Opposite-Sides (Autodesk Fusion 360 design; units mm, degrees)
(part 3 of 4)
sketch "Rail seat underside (1)" plane through (11.9, 0, 0) normal (1, 0, 0) x axis (0, 0, -1)
  line L1 (-50.9, 96) -> (-50.9, 75)
  line L2 (-55, 96) -> (-50.9, 96)
  line L3 (-55, 75) -> (-55, 96)
  line L4 (-50.9, 75) -> (-55, 75)
extrude "Extrude7" cut sketch "Rail seat underside (1)" along normal blind 12.2
work_plane "WorkPlane8" AlongDistance 54.9 ExtraOffset 0
sketch "M5 rail bore (1)" plane through (0, 0, 54.9) normal (0, 0, 1) x axis (1, 0, 0)
  circle C1 centre (18, 85) radius 2.7
extrude "Extrude8" cut sketch "M5 rail bore (1)" along normal blind 9.2
work_plane "WorkPlane9" AlongDistance 54.9 ExtraOffset 0
sketch "Rail bore print-up roof (1)" plane through (0, 0, 54.9) normal (0, 0, 1) x axis (1, 0, 0)
  line L1 (19.9092, 86.9092) -> (19.9092, 83.0908)
  line L2 (21.8184, 85) -> (19.9092, 86.9092)
  line L3 (19.9092, 83.0908) -> (21.8184, 85)
extrude "Extrude9" cut sketch "Rail bore print-up roof (1)" along normal blind 9.2
work_plane "WorkPlane1" AlongDistance 50 ExtraOffset 0
sketch "Top rail M5x14 (1, 1)" plane through (0, 0, 50) normal (0, 0, 1) x axis (1, 0, 0)
  circle C1 centre (18, 85) radius 2.5
extrude "Extrude1" new body sketch "Top rail M5x14 (1, 1)" along normal blind 14 bodies "HARDWARE Top rail M5x14 (1, 1)"
work_plane "WorkPlane2" AlongDistance 64 ExtraOffset 0
sketch "Button head" plane through (0, 0, 64) normal (0, 0, 1) x axis (1, 0, 0)
  circle C1 centre (18, 85) radius 4.25
extrude "Extrude2" add sketch "Button head" along normal blind 5
work_plane "WorkPlane10" AlongDistance 11.9 ExtraOffset 0
sketch "Main bearing seat" plane through (11.9, 0, 0) normal (1, 0, 0) x axis (0, 0, -1)
  circle C1 centre (-30, 0) radius 10.15
extrude "Extrude10" cut sketch "Main bearing seat" along normal blind 12.2
work_plane "WorkPlane11" AlongDistance 11.9 ExtraOffset 0
sketch "Brace mounting clearance" plane through (11.9, 0, 0) normal (1, 0, 0) x axis (0, 0, -1)
  circle C1 centre (-35, -60) radius 1.7
work_plane "WorkPlane12" AlongDistance 11.9 ExtraOffset 0
sketch "Brace mounting clearance (1)" plane through (11.9, 0, 0) normal (1, 0, 0) x axis (0, 0, -1)
  circle C1 centre (-45, -60) radius 1.7
work_plane "WorkPlane13" AlongDistance 11.9 ExtraOffset 0
sketch "Brace mounting clearance (2)" plane through (11.9, 0, 0) normal (1, 0, 0) x axis (0, 0, -1)
  circle C1 centre (-35, 60) radius 1.7
work_plane "WorkPlane14" AlongDistance 11.9 ExtraOffset 0
sketch "Brace mounting clearance (3)" plane through (11.9, 0, 0) normal (1, 0, 0) x axis (0, 0, -1)
  circle C1 centre (-45, 60) radius 1.7
work_plane "WorkPlane15" AlongDistance 11.9 ExtraOffset 0
sketch "Local measured pot and wire opening" plane through (11.9, 0, 0) normal (1, 0, 0) x axis (0, 0, -1)
  line L1 (5.5307, 7.9631) -> (6, 8)
  line L2 (5.0729, 7.8532) -> (5.5307, 7.9631)
  line L3 (4.638, 7.673) -> (5.0729, 7.8532)
  line L4 (4.2366, 7.4271) -> (4.638, 7.673)
  line L5 (3.8787, 7.1213) -> (4.2366, 7.4271)
  line L6 (3.5729, 6.7634) -> (3.8787, 7.1213)
  line L7 (3.327, 6.362) -> (3.5729, 6.7634)
  line L8 (3.1468, 5.9271) -> (3.327, 6.362)
  line L9 (3.0369, 5.4693) -> (3.1468, 5.9271)
  line L10 (3, 5) -> (3.0369, 5.4693)
  line L11 (3, -5) -> (3, 5)
  line L12 (3.0369, -5.4693) -> (3, -5)
  line L13 (3.1468, -5.9271) -> (3.0369, -5.4693)
  line L14 (3.327, -6.362) -> (3.1468, -5.9271)
  line L15 (3.5729, -6.7634) -> (3.327, -6.362)
  line L16 (3.8787, -7.1213) -> (3.5729, -6.7634)
  line L17 (4.2366, -7.4271) -> (3.8787, -7.1213)
  line L18 (4.638, -7.673) -> (4.2366, -7.4271)
  line L19 (5.0729, -7.8532) -> (4.638, -7.673)
  line L20 (5.5307, -7.9631) -> (5.0729, -7.8532)
  line L21 (6, -8) -> (5.5307, -7.9631)
  line L22 (24, -8) -> (6, -8)
  line L23 (24.4693, -7.9631) -> (24, -8)
  line L24 (24.9271, -7.8532) -> (24.4693, -7.9631)
  line L25 (25.362, -7.673) -> (24.9271, -7.8532)
  line L26 (25.7634, -7.4271) -> (25.362, -7.673)
  line L27 (26.1213, -7.1213) -> (25.7634, -7.4271)
  line L28 (26.4271, -6.7634) -> (26.1213, -7.1213)
  line L29 (26.673, -6.362) -> (26.4271, -6.7634)
  line L30 (26.8532, -5.9271) -> (26.673, -6.362)
  line L31 (26.9631, -5.4693) -> (26.8532, -5.9271)
  line L32 (27, -5) -> (26.9631, -5.4693)
  line L33 (27, 5) -> (27, -5)
  line L34 (26.9631, 5.4693) -> (27, 5)
  line L35 (26.8532, 5.9271) -> (26.9631, 5.4693)
  line L36 (26.673, 6.362) -> (26.8532, 5.9271)
  line L37 (26.4271, 6.7634) -> (26.673, 6.362)
  line L38 (26.1213, 7.1213) -> (26.4271, 6.7634)
  line L39 (25.7634, 7.4271) -> (26.1213, 7.1213)
  line L40 (25.362, 7.673) -> (25.7634, 7.4271)
  line L41 (24.9271, 7.8532) -> (25.362, 7.673)
  line L42 (24.4693, 7.9631) -> (24.9271, 7.8532)
  line L43 (24, 8) -> (24.4693, 7.9631)
  line L44 (6, 8) -> (24, 8)
extrude "Extrude15" cut sketch "Local measured pot and wire opening" along normal blind 10.3
work_plane "WorkPlane16" AlongDistance 22 ExtraOffset 0
sketch "Pot panel rebate" plane through (22, 0, 0) normal (1, 0, 0) x axis (0, 0, -1)
  line L1 (2.5307, 23.9631) -> (3, 24)
  line L2 (2.0729, 23.8532) -> (2.5307, 23.9631)
  line L3 (1.638, 23.673) -> (2.0729, 23.8532)
  line L4 (1.2366, 23.4271) -> (1.638, 23.673)
  line L5 (0.8787, 23.1213) -> (1.2366, 23.4271)
  line L6 (0.5729, 22.7634) -> (0.8787, 23.1213)
  line L7 (0.327, 22.362) -> (0.5729, 22.7634)
  line L8 (0.1468, 21.9271) -> (0.327, 22.362)
  line L9 (0.0369, 21.4693) -> (0.1468, 21.9271)
  line L10 (0, 21) -> (0.0369, 21.4693)
  line L11 (0, -21) -> (0, 21)
  line L12 (0.0369, -21.4693) -> (0, -21)
  line L13 (0.1468, -21.9271) -> (0.0369, -21.4693)
  line L14 (0.327, -22.362) -> (0.1468, -21.9271)
  line L15 (0.5729, -22.7634) -> (0.327, -22.362)
  line L16 (0.8787, -23.1213) -> (0.5729, -22.7634)
  line L17 (1.2366, -23.4271) -> (0.8787, -23.1213)
  line L18 (1.638, -23.673) -> (1.2366, -23.4271)
  line L19 (2.0729, -23.8532) -> (1.638, -23.673)
  line L20 (2.5307, -23.9631) -> (2.0729, -23.8532)
  line L21 (3, -24) -> (2.5307, -23.9631)
  line L22 (27, -24) -> (3, -24)
  line L23 (27.4693, -23.9631) -> (27, -24)
  line L24 (27.9271, -23.8532) -> (27.4693, -23.9631)
  line L25 (28.362, -23.673) -> (27.9271, -23.8532)
  line L26 (28.7634, -23.4271) -> (28.362, -23.673)
  line L27 (29.1213, -23.1213) -> (28.7634, -23.4271)
  line L28 (29.4271, -22.7634) -> (29.1213, -23.1213)
  line L29 (29.673, -22.362) -> (29.4271, -22.7634)
  line L30 (29.8532, -21.9271) -> (29.673, -22.362)
  line L31 (29.9631, -21.4693) -> (29.8532, -21.9271)
  line L32 (30, -21) -> (29.9631, -21.4693)
  line L33 (30, 21) -> (30, -21)
  line L34 (29.9631, 21.4693) -> (30, 21)
  line L35 (29.8532, 21.9271) -> (29.9631, 21.4693)
  line L36 (29.673, 22.362) -> (29.8532, 21.9271)
  line L37 (29.4271, 22.7634) -> (29.673, 22.362)
  line L38 (29.1213, 23.1213) -> (29.4271, 22.7634)
  line L39 (28.7634, 23.4271) -> (29.1213, 23.1213)
  line L40 (28.362, 23.673) -> (28.7634, 23.4271)
  line L41 (27.9271, 23.8532) -> (28.362, 23.673)
  line L42 (27.4693, 23.9631) -> (27.9271, 23.8532)
  line L43 (27, 24) -> (27.4693, 23.9631)
  line L44 (3, 24) -> (27, 24)
extrude "Extrude16" cut sketch "Pot panel rebate" along normal blind 2.1
work_plane "WorkPlane17" AlongDistance 12.5 ExtraOffset 0
sketch "Sensor panel insert and screw relief" plane through (12.5, 0, 0) normal (1, 0, 0) x axis (0, 0, -1)
  circle C1 centre (15.15, -16) radius 2
extrude "Extrude17" cut sketch "Sensor panel insert and screw relief" along normal blind 9.6
work_plane "WorkPlane18" AlongDistance 12.5 ExtraOffset 0
sketch "Sensor panel insert and screw relief (1)" plane through (12.5, 0, 0) normal (1, 0, 0) x axis (0, 0, -1)
  circle C1 centre (15.15, 16) radius 2
extrude "Extrude18" cut sketch "Sensor panel insert and screw relief (1)" along normal blind 9.6
work_plane "WorkPlane1" AlongDistance -12 ExtraOffset 0
sketch "Rigid plate spacing block" plane through (-12, 0, 0) normal (1, 0, 0) x axis (0, 0, -1)
  line L1 (-30, -52) -> (-30, -68)
  line L2 (-50, -52) -> (-30, -52)
  line L3 (-50, -68) -> (-50, -52)
  line L4 (-30, -68) -> (-50, -68)
extrude "Extrude1" new body sketch "Rigid plate spacing block" along normal blind 24 bodies "P30 Crossbrace -60"
work_plane "WorkPlane2" AlongDistance -12.1 ExtraOffset 0
sketch "Brace M3 insert relief" plane through (-12.1, 0, 0) normal (1, 0, 0) x axis (0, 0, -1)
  circle C1 centre (-35, -60) radius 2
extrude "Extrude2" cut sketch "Brace M3 insert relief" along normal blind 8.6
work_plane "WorkPlane1" AlongDistance -24 ExtraOffset 0
sketch "Brace M3x20 (-60, -1, 35)" plane through (-24, 0, 0) normal (1, 0, 0) x axis (0, 0, -1)
  circle C1 centre (-35, -60) radius 1.5
extrude "Extrude1" new body sketch "Brace M3x20 (-60, -1, 35)" along normal blind 20 bodies "HARDWARE Brace M3x20 (-60, -1, 35)"
work_plane "WorkPlane2" AlongDistance -27 ExtraOffset 0
sketch "Button head" plane through (-27, 0, 0) normal (1, 0, 0) x axis (0, 0, -1)
  circle C1 centre (-35, -60) radius 2.75
extrude "Extrude2" add sketch "Button head" along normal blind 3
work_plane "WorkPlane3" AlongDistance -12.1 ExtraOffset 0
sketch "Brace M3 insert relief (1)" plane through (-12.1, 0, 0) normal (1, 0, 0) x axis (0, 0, -1)
  circle C1 centre (-45, -60) radius 2
extrude "Extrude3" cut sketch "Brace M3 insert relief (1)" along normal blind 8.6
work_plane "WorkPlane1" AlongDistance -24 ExtraOffset 0
sketch "Brace M3x20 (-60, -1, 45)" plane through (-24, 0, 0) normal (1, 0, 0) x axis (0, 0, -1)
  circle C1 centre (-45, -60) radius 1.5
extrude "Extrude1" new body sketch "Brace M3x20 (-60, -1, 45)" along normal blind 20 bodies "HARDWARE Brace M3x20 (-60, -1, 45)"
work_plane "WorkPlane2" AlongDistance -27 ExtraOffset 0
sketch "Button head" plane through (-27, 0, 0) normal (1, 0, 0) x axis (0, 0, -1)
  circle C1 centre (-45, -60) radius 2.75
extrude "Extrude2" add sketch "Button head" along normal blind 3
work_plane "WorkPlane4" AlongDistance 3.5 ExtraOffset 0
sketch "Brace M3 insert relief (2)" plane through (3.5, 0, 0) normal (1, 0, 0) x axis (0, 0, -1)
  circle C1 centre (-35, -60) radius 2
extrude "Extrude4" cut sketch "Brace M3 insert relief (2)" along normal blind 8.6
work_plane "WorkPlane1" AlongDistance 4 ExtraOffset 0
sketch "Brace M3x20 (-60, 1, 35)" plane through (4, 0, 0) normal (1, 0, 0) x axis (0, 0, -1)
  circle C1 centre (-35, -60) radius 1.5
extrude "Extrude1" new body sketch "Brace M3x20 (-60, 1, 35)" along normal blind 20 bodies "HARDWARE Brace M3x20 (-60, 1, 35)"
work_plane "WorkPlane2" AlongDistance 24 ExtraOffset 0
sketch "Button head" plane through (24, 0, 0) normal (1, 0, 0) x axis (0, 0, -1)
  circle C1 centre (-35, -60) radius 2.75
extrude "Extrude2" add sketch "Button head" along normal blind 3
work_plane "WorkPlane5" AlongDistance 3.5 ExtraOffset 0
sketch "Brace M3 insert relief (3)" plane through (3.5, 0, 0) normal (1, 0, 0) x axis (0, 0, -1)
  circle C1 centre (-45, -60) radius 2
extrude "Extrude5" cut sketch "Brace M3 insert relief (3)" along normal blind 8.6
work_plane "WorkPlane1" AlongDistance 4 ExtraOffset 0
sketch "Brace M3x20 (-60, 1, 45)" plane through (4, 0, 0) normal (1, 0, 0) x axis (0, 0, -1)
  circle C1 centre (-45, -60) radius 1.5
extrude "Extrude1" new body sketch "Brace M3x20 (-60, 1, 45)" along normal blind 20 bodies "HARDWARE Brace M3x20 (-60, 1, 45)"
work_plane "WorkPlane2" AlongDistance 24 ExtraOffset 0
sketch "Button head" plane through (24, 0, 0) normal (1, 0, 0) x axis (0, 0, -1)
  circle C1 centre (-45, -60) radius 2.75
extrude "Extrude2" add sketch "Button head" along normal blind 3
work_plane "WorkPlane1" AlongDistance -12 ExtraOffset 0
sketch "Rigid plate spacing block" plane through (-12, 0, 0) normal (1, 0, 0) x axis (0, 0, -1)
  line L1 (-30, 68) -> (-30, 52)
  line L2 (-50, 68) -> (-30, 68)
  line L3 (-50, 52) -> (-50, 68)
  line L4 (-30, 52) -> (-50, 52)
extrude "Extrude1" new body sketch "Rigid plate spacing block" along normal blind 24 bodies "P30 Crossbrace 60"
work_plane "WorkPlane2" AlongDistance -12.1 ExtraOffset 0
sketch "Brace M3 insert relief" plane through (-12.1, 0, 0) normal (1, 0, 0) x axis (0, 0, -1)
  circle C1 centre (-35, 60) radius 2
extrude "Extrude2" cut sketch "Brace M3 insert relief" along normal blind 8.6
work_plane "WorkPlane1" AlongDistance -24 ExtraOffset 0
sketch "Brace M3x20 (60, -1, 35)" plane through (-24, 0, 0) normal (1, 0, 0) x axis (0, 0, -1)
  circle C1 centre (-35, 60) radius 1.5
extrude "Extrude1" new body sketch "Brace M3x20 (60, -1, 35)" along normal blind 20 bodies "HARDWARE Brace M3x20 (60, -1, 35)"
work_plane "WorkPlane2" AlongDistance -27 ExtraOffset 0
sketch "Button head" plane through (-27, 0, 0) normal (1, 0, 0) x axis (0, 0, -1)
  circle C1 centre (-35, 60) radius 2.75
extrude "Extrude2" add sketch "Button head" along normal blind 3
work_plane "WorkPlane3" AlongDistance -12.1 ExtraOffset 0
sketch "Brace M3 insert relief (1)" plane through (-12.1, 0, 0) normal (1, 0, 0) x axis (0, 0, -1)
  circle C1 centre (-45, 60) radius 2
extrude "Extrude3" cut sketch "Brace M3 insert relief (1)" along normal blind 8.6
work_plane "WorkPlane1" AlongDistance -24 ExtraOffset 0
sketch "Brace M3x20 (60, -1, 45)" plane through (-24, 0, 0) normal (1, 0, 0) x axis (0, 0, -1)
  circle C1 centre (-45, 60) radius 1.5
extrude "Extrude1" new body sketch "Brace M3x20 (60, -1, 45)" along normal blind 20 bodies "HARDWARE Brace M3x20 (60, -1, 45)"
work_plane "WorkPlane2" AlongDistance -27 ExtraOffset 0
sketch "Button head" plane through (-27, 0, 0) normal (1, 0, 0) x axis (0, 0, -1)
  circle C1 centre (-45, 60) radius 2.75
extrude "Extrude2" add sketch "Button head" along normal blind 3
work_plane "WorkPlane4" AlongDistance 3.5 ExtraOffset 0
sketch "Brace M3 insert relief (2)" plane through (3.5, 0, 0) normal (1, 0, 0) x axis (0, 0, -1)
  circle C1 centre (-35, 60) radius 2
extrude "Extrude4" cut sketch "Brace M3 insert relief (2)" along normal blind 8.6
work_plane "WorkPlane1" AlongDistance 4 ExtraOffset 0
sketch "Brace M3x20 (60, 1, 35)" plane through (4, 0, 0) normal (1, 0, 0) x axis (0, 0, -1)
  circle C1 centre (-35, 60) radius 1.5
extrude "Extrude1" new body sketch "Brace M3x20 (60, 1, 35)" along normal blind 20 bodies "HARDWARE Brace M3x20 (60, 1, 35)"
work_plane "WorkPlane2" AlongDistance 24 ExtraOffset 0
sketch "Button head" plane through (24, 0, 0) normal (1, 0, 0) x axis (0, 0, -1)
  circle C1 centre (-35, 60) radius 2.75
extrude "Extrude2" add sketch "Button head" along normal blind 3
work_plane "WorkPlane5" AlongDistance 3.5 ExtraOffset 0
sketch "Brace M3 insert relief (3)" plane through (3.5, 0, 0) normal (1, 0, 0) x axis (0, 0, -1)
  circle C1 centre (-45, 60) radius 2
extrude "Extrude5" cut sketch "Brace M3 insert relief (3)" along normal blind 8.6
work_plane "WorkPlane1" AlongDistance 4 ExtraOffset 0
sketch "Brace M3x20 (60, 1, 45)" plane through (4, 0, 0) normal (1, 0, 0) x axis (0, 0, -1)
  circle C1 centre (-45, 60) radius 1.5
extrude "Extrude1" new body sketch "Brace M3x20 (60, 1, 45)" along normal blind 20 bodies "HARDWARE Brace M3x20 (60, 1, 45)"
work_plane "WorkPlane2" AlongDistance 24 ExtraOffset 0
sketch "Button head" plane through (24, 0, 0) normal (1, 0, 0) x axis (0, 0, -1)
  circle C1 centre (-45, 60) radius 2.75
extrude "Extrude2" add sketch "Button head" along normal blind 3
work_plane "WorkPlane1" AlongDistance 22.8923 ExtraOffset 0
sketch "Supported stop with shear spigot" plane through (0, 0, 22.8923) normal (0, 0, 1) x axis (1, 0, 0)
  line L1 (-17, -30.3109) -> (-17, -36.3109)
  line L2 (-12, -30.3109) -> (-17, -30.3109)
  line L3 (-12, -26.3109) -> (-12, -30.3109)
  line L4 (-8, -28.3109) -> (-12, -26.3109)
  line L5 (0, -28.3109) -> (-8, -28.3109)
  line L6 (0, -36.3109) -> (0, -28.3109)
  line L7 (-17, -36.3109) -> (0, -36.3109)
  line L8 (10, -36.3109) -> (-30, -36.3109)
revolve "Revolve1" sketch "Supported stop with shear spigot" AlongAngle 360 bodies "P31 Positively located stop -1"
work_plane "WorkPlane2" AlongDistance -17.1 ExtraOffset 0
sketch "Stop insert and deep screw-tip relief" plane through (-17.1, 0, 0) normal (1, 0, 0) x axis (0, 0, -1)
  circle C1 centre (-22.8923, -36.3109) radius 2
extrude "Extrude1" cut sketch "Stop insert and deep screw-tip relief" along normal blind 13.6
work_plane "WorkPlane1" AlongDistance 22.8923 ExtraOffset 0
sketch "Supported stop with shear spigot" plane through (0, 0, 22.8923) normal (0, 0, 1) x axis (1, 0, 0)
  line L1 (-17, 42.3109) -> (-17, 36.3109)
  line L2 (-12, 42.3109) -> (-17, 42.3109)
  line L3 (-12, 46.3109) -> (-12, 42.3109)
  line L4 (-8, 44.3109) -> (-12, 46.3109)
  line L5 (0, 44.3109) -> (-8, 44.3109)
  line L6 (0, 36.3109) -> (0, 44.3109)
  line L7 (-17, 36.3109) -> (0, 36.3109)
  line L8 (10, 36.3109) -> (-30, 36.3109)
revolve "Revolve1" sketch "Supported stop with shear spigot" AlongAngle 360 bodies "P31 Positively located stop 1"
work_plane "WorkPlane2" AlongDistance -17.1 ExtraOffset 0
sketch "Stop insert and deep screw-tip relief" plane through (-17.1, 0, 0) normal (1, 0, 0) x axis (0, 0, -1)
  circle C1 centre (-22.8923, 36.3109) radius 2
extrude "Extrude1" cut sketch "Stop insert and deep screw-tip relief" along normal blind 13.6
work_plane "WorkPlane1" AlongDistance -38 ExtraOffset 0
sketch "Left drive and round journals" plane through (-38, 0, 0) normal (1, 0, 0) x axis (0, 0, -1)
  circle C1 centre (-30, 0) radius 6
extrude "Extrude1" new body sketch "Left drive and round journals" along normal blind 63.35 bodies "P05S Shaft lower half"
work_plane "WorkPlane2" AlongDistance -38.1 ExtraOffset 0
sketch "Left drive D flat" plane through (-38.1, 0, 0) normal (1, 0, 0) x axis (0, 0, -1)
  line L1 (-23.9, 6.1) -> (-23.9, 4.8)
  line L2 (-36.1, 6.1) -> (-23.9, 6.1)
  line L3 (-36.1, 4.8) -> (-36.1, 6.1)
  line L4 (-23.9, 4.8) -> (-36.1, 4.8)
extrude "Extrude2" cut sketch "Left drive D flat" along normal blind 12.75
work_plane "WorkPlane3" AlongDistance -11.8 ExtraOffset 0
sketch "Central structural D section" plane through (-11.8, 0, 0) normal (1, 0, 0) x axis (0, 0, -1)
  line L1 (-34.6637, 6.5) -> (-25.3363, 6.5)
  arc A1 centre (-30, 0) radius 8 clockwise from (-25.3363, 6.5) to (-34.6637, 6.5)
extrude "Extrude3" add sketch "Central structural D section" along normal blind 23.6
work_plane "WorkPlane4" AlongDistance 25.35 ExtraOffset 0
sketch "Pass-through right D drive" plane through (25.35, 0, 0) normal (1, 0, 0) x axis (0, 0, -1)
  line L1 (-32.4, 3.2) -> (-27.6, 3.2)
  arc A1 centre (-30, 0) radius 4 clockwise from (-27.6, 3.2) to (-32.4, 3.2)
extrude "Extrude4" add sketch "Pass-through right D drive" along normal blind 11
work_plane "WorkPlane5" AlongDistance -38.1 ExtraOffset 0
sketch "Axial retaining insert" plane through (-38.1, 0, 0) normal (1, 0, 0) x axis (0, 0, -1)
  circle C1 centre (-30, 0) radius 2
extrude "Extrude5" cut sketch "Axial retaining insert" along normal blind 6.9
work_plane "WorkPlane6" AlongDistance -6.8 ExtraOffset 0
sketch "Shaft half insert" plane through (0, -6.8, 0) normal (0, 1, 0) x axis (1, 0, 0)
  circle C1 centre (-7.5, -30) radius 2
extrude "Extrude6" cut sketch "Shaft half insert" along normal blind 6.9
work_plane "WorkPlane7" AlongDistance -0.1 ExtraOffset 0
sketch "Shaft half screw" plane through (0, -0.1, 0) normal (0, 1, 0) x axis (1, 0, 0)
  circle C1 centre (-7.5, -30) radius 1.7
extrude "Extrude7" cut sketch "Shaft half screw" along normal blind 6.7
work_plane "WorkPlane8" AlongDistance 3.5 ExtraOffset 0
sketch "Flush joining head" plane through (0, 3.5, 0) normal (0, 1, 0) x axis (1, 0, 0)
  circle C1 centre (-7.5, -30) radius 3.1
extrude "Extrude8" cut sketch "Flush joining head" along normal blind 3.1
work_plane "WorkPlane1" AlongDistance -4.5 ExtraOffset 0
sketch "Shaft joining M3x8 -8" plane through (0, -4.5, 0) normal (0, 1, 0) x axis (1, 0, 0)
  circle C1 centre (-8, -30) radius 1.5
extrude "Extrude1" new body sketch "Shaft joining M3x8 -8" along normal blind 8 bodies "HARDWARE Shaft joining M3x8 -8"
work_plane "WorkPlane2" AlongDistance 3.5 ExtraOffset 0
sketch "Button head" plane through (0, 3.5, 0) normal (0, 1, 0) x axis (1, 0, 0)
  circle C1 centre (-8, -30) radius 2.75
extrude "Extrude2" add sketch "Button head" along normal blind 3
work_plane "WorkPlane9" AlongDistance -6.8 ExtraOffset 0
sketch "Shaft half insert (1)" plane through (0, -6.8, 0) normal (0, 1, 0) x axis (1, 0, 0)
  circle C1 centre (7.5, -30) radius 2
extrude "Extrude9" cut sketch "Shaft half insert (1)" along normal blind 6.9
work_plane "WorkPlane10" AlongDistance -0.1 ExtraOffset 0
sketch "Shaft half screw (1)" plane through (0, -0.1, 0) normal (0, 1, 0) x axis (1, 0, 0)
  circle C1 centre (7.5, -30) radius 1.7
extrude "Extrude10" cut sketch "Shaft half screw (1)" along normal blind 6.7
work_plane "WorkPlane11" AlongDistance 3.5 ExtraOffset 0
sketch "Flush joining head (1)" plane through (0, 3.5, 0) normal (0, 1, 0) x axis (1, 0, 0)
  circle C1 centre (7.5, -30) radius 3.1
extrude "Extrude11" cut sketch "Flush joining head (1)" along normal blind 3.1
work_plane "WorkPlane1" AlongDistance -4.5 ExtraOffset 0
sketch "Shaft joining M3x8 8" plane through (0, -4.5, 0) normal (0, 1, 0) x axis (1, 0, 0)
  circle C1 centre (8, -30) radius 1.5
extrude "Extrude1" new body sketch "Shaft joining M3x8 8" along normal blind 8 bodies "HARDWARE Shaft joining M3x8 8"
work_plane "WorkPlane2" AlongDistance 3.5 ExtraOffset 0
sketch "Button head" plane through (0, 3.5, 0) normal (0, 1, 0) x axis (1, 0, 0)
  circle C1 centre (8, -30) radius 2.75
extrude "Extrude2" add sketch "Button head" along normal blind 3
work_plane "WorkPlane12" AlongDistance -1.6 ExtraOffset 0
sketch "Central loose key pocket" plane through (-1.6, 0, 0) normal (1, 0, 0) x axis (0, 0, -1)
  line L1 (-26, 1.6) -> (-26, -1.6)
  line L2 (-34, 1.6) -> (-26, 1.6)
  line L3 (-34, -1.6) -> (-34, 1.6)
  line L4 (-26, -1.6) -> (-34, -1.6)
extrude "Extrude12" cut sketch "Central loose key pocket" along normal blind 3.2
split "Split1" bodies "P05S Shaft upper half"
work_plane "WorkPlane1" AlongDistance -1.5 ExtraOffset 0
sketch "Loose printable key" plane through (-1.5, 0, 0) normal (1, 0, 0) x axis (0, 0, -1)
  line L1 (-26.1, 1.5) -> (-26.1, -1.5)
  line L2 (-33.9, 1.5) -> (-26.1, 1.5)
  line L3 (-33.9, -1.5) -> (-33.9, 1.5)
  line L4 (-26.1, -1.5) -> (-33.9, -1.5)
extrude "Extrude1" new body sketch "Loose printable key" along normal blind 3 bodies "P28 Shaft alignment key"
work_plane "WorkPlane1" AlongDistance -40 ExtraOffset 0
sketch "Axial retaining cap" plane through (-40, 0, 0) normal (1, 0, 0) x axis (0, 0, -1)
  circle C1 centre (-30, 0) radius 10
extrude "Extrude1" new body sketch "Axial retaining cap" along normal blind 2 bodies "P06 Shaft retaining cap"
work_plane "WorkPlane2" AlongDistance -40.1 ExtraOffset 0
sketch "M3 passage" plane through (-40.1, 0, 0) normal (1, 0, 0) x axis (0, 0, -1)
  circle C1 centre (-30, 0) radius 1.7
extrude "Extrude2" cut sketch "M3 passage" along normal blind 2.2
work_plane "WorkPlane1" AlongDistance -40 ExtraOffset 0
sketch "Main shaft cap M3x8" plane through (-40, 0, 0) normal (1, 0, 0) x axis (0, 0, -1)
  circle C1 centre (-30, 0) radius 1.5
extrude "Extrude1" new body sketch "Main shaft cap M3x8" along normal blind 8 bodies "HARDWARE Main shaft cap M3x8"
work_plane "WorkPlane2" AlongDistance -43 ExtraOffset 0
sketch "Button head" plane through (-43, 0, 0) normal (1, 0, 0) x axis (0, 0, -1)
  circle C1 centre (-30, 0) radius 2.75
extrude "Extrude2" add sketch "Button head" along normal blind 3
work_plane "WorkPlane1" AlongDistance -7 ExtraOffset 0
sketch "Main lever hub" plane through (-7, 0, 0) normal (1, 0, 0) x axis (0, 0, -1)
  circle C1 centre (-30, 0) radius 22
extrude "Extrude1" new body sketch "Main lever hub" along normal blind 14 bodies "P07S Planar lever rotor with lower stop lug"
work_plane "WorkPlane2" AlongDistance -7 ExtraOffset 0
sketch "Continuous grip stem" plane through (-7, 0, 0) normal (1, 0, 0) x axis (0, 0, -1)
  line L1 (-25, 14) -> (-25, -14)
  line L2 (-60, 11) -> (-25, 14)
  line L3 (-115, 7) -> (-60, 11)
  line L4 (-160, 7) -> (-115, 7)
  line L5 (-160, -7) -> (-160, 7)
  line L6 (-115, -7) -> (-160, -7)
  line L7 (-60, -11) -> (-115, -7)
  line L8 (-25, -14) -> (-60, -11)
extrude "Extrude2" add sketch "Continuous grip stem" along normal blind 14
work_plane "WorkPlane3" AlongDistance -7 ExtraOffset 0
sketch "Broad lower stop root" plane through (-7, 0, 0) normal (1, 0, 0) x axis (0, 0, -1)
  line L1 (0, -6) -> (-15, -11)
  line L2 (0, 6) -> (0, -6)
  line L3 (-15, 11) -> (0, 6)
  line L4 (-15, -11) -> (-15, 11)
extrude "Extrude3" add sketch "Broad lower stop root" along normal blind 14
work_plane "WorkPlane4" AlongDistance -7 ExtraOffset 0
sketch "Round lower stop nose" plane through (-7, 0, 0) normal (1, 0, 0) x axis (0, 0, -1)
  circle C1 centre (0, 0) radius 5
extrude "Extrude4" add sketch "Round lower stop nose" along normal blind 14
work_plane "WorkPlane5" AlongDistance -7.1 ExtraOffset 0
sketch "Rotor keyed socket" plane through (-7.1, 0, 0) normal (1, 0, 0) x axis (0, 0, -1)
  line L1 (-34.6247, 6.65) -> (-25.3753, 6.65)
  arc A1 centre (-30, 0) radius 8.1 clockwise from (-25.3753, 6.65) to (-34.6247, 6.65)
extrude "Extrude5" cut sketch "Rotor keyed socket" along normal blind 14.2
work_plane "WorkPlane6" AlongDistance -7.1 ExtraOffset 0
sketch "Grip screw clearance" plane through (-7.1, 0, 0) normal (1, 0, 0) x axis (0, 0, -1)
  circle C1 centre (-145, 0) radius 1.7
extrude "Extrude6" cut sketch "Grip screw clearance" along normal blind 14.2
work_plane "WorkPlane7" AlongDistance -7.1 ExtraOffset 0
sketch "Grip screw clearance (1)" plane through (-7.1, 0, 0) normal (1, 0, 0) x axis (0, 0, -1)
  circle C1 centre (-155, 0) radius 1.7
extrude "Extrude7" cut sketch "Grip screw clearance (1)" along normal blind 14.2
work_plane "WorkPlane8" AlongDistance -5 ExtraOffset 0
sketch "Rotor clamp head seat" plane through (-5, 0, 0) normal (1, 0, 0) x axis (0, 0, -1)
  line L1 (-25, 22.5) -> (-25, 21.4)
  line L2 (-35, 22.5) -> (-25, 22.5)
  line L3 (-35, 21.4) -> (-35, 22.5)
  line L4 (-25, 21.4) -> (-35, 21.4)
extrude "Extrude8" add sketch "Rotor clamp head seat" along normal blind 10
work_plane "WorkPlane9" AlongDistance 15.7 ExtraOffset 0
sketch "Rotor clamp insert" plane through (0, 15.7, 0) normal (0, 1, 0) x axis (1, 0, 0)
  circle C1 centre (0, -30) radius 2
extrude "Extrude9" cut sketch "Rotor clamp insert" along normal blind 6.8
work_plane "WorkPlane10" AlongDistance 6.6 ExtraOffset 0
sketch "Rotor clamp tip passage" plane through (0, 6.6, 0) normal (0, 1, 0) x axis (1, 0, 0)
  circle C1 centre (0, -30) radius 1.7
extrude "Extrude10" cut sketch "Rotor clamp tip passage" along normal blind 9.2
work_plane "WorkPlane11" AlongDistance 15.7 ExtraOffset 0
sketch "Radial bore print roof" plane through (0, 15.7, 0) normal (0, 1, 0) x axis (1, 0, 0)
  line L1 (1.4142, -31.4142) -> (1.4142, -28.5858)
  line L2 (2.8284, -30) -> (1.4142, -31.4142)
  line L3 (1.4142, -28.5858) -> (2.8284, -30)
extrude "Extrude11" cut sketch "Radial bore print roof" along normal blind 6.8
work_plane "WorkPlane12" AlongDistance 6.6 ExtraOffset 0
sketch "Radial bore print roof (1)" plane through (0, 6.6, 0) normal (0, 1, 0) x axis (1, 0, 0)
  line L1 (1.2021, -31.2021) -> (1.2021, -28.7979)
  line L2 (2.4042, -30) -> (1.2021, -31.2021)
  line L3 (1.2021, -28.7979) -> (2.4042, -30)
extrude "Extrude12" cut sketch "Radial bore print roof (1)" along normal blind 9.2
work_plane "WorkPlane1" AlongDistance 6.5 ExtraOffset 0
sketch "Rotor clamp M3x16" plane through (0, 6.5, 0) normal (0, 1, 0) x axis (1, 0, 0)
  circle C1 centre (0, -30) radius 1.5
extrude "Extrude1" new body sketch "Rotor clamp M3x16" along normal blind 16 bodies "HARDWARE Rotor clamp M3x16"
work_plane "WorkPlane2" AlongDistance 22.5 ExtraOffset 0
sketch "Button head" plane through (0, 22.5, 0) normal (0, 1, 0) x axis (1, 0, 0)
  circle C1 centre (0, -30) radius 2.75
extrude "Extrude2" add sketch "Button head" along normal blind 3
work_plane "WorkPlane1" AlongDistance -11.8 ExtraOffset 0
sketch "Independent thrust spacer" plane through (-11.8, 0, 0) normal (1, 0, 0) x axis (0, 0, -1)
  circle C1 centre (-30, 0) radius 10
extrude "Extrude1" new body sketch "Independent thrust spacer" along normal blind 4.8 bodies "P23 Rotor thrust spacer"
work_plane "WorkPlane2" AlongDistance -11.9 ExtraOffset 0
sketch "D clearance" plane through (-11.9, 0, 0) normal (1, 0, 0) x axis (0, 0, -1)
  line L1 (-34.6403, 6.7) -> (-25.3597, 6.7)
  arc A1 centre (-30, 0) radius 8.15 clockwise from (-25.3597, 6.7) to (-34.6403, 6.7)
extrude "Extrude2" cut sketch "D clearance" along normal blind 5
work_plane "WorkPlane1" AlongDistance 7 ExtraOffset 0
sketch "Independent thrust spacer" plane through (7, 0, 0) normal (1, 0, 0) x axis (0, 0, -1)
  circle C1 centre (-30, 0) radius 10
extrude "Extrude1" new body sketch "Independent thrust spacer" along normal blind 4.8 bodies "P24 Rotor thrust spacer"
work_plane "WorkPlane2" AlongDistance 6.9 ExtraOffset 0
sketch "D clearance" plane through (6.9, 0, 0) normal (1, 0, 0) x axis (0, 0, -1)
  line L1 (-34.6403, 6.7) -> (-25.3597, 6.7)
  arc A1 centre (-30, 0) radius 8.15 clockwise from (-25.3597, 6.7) to (-34.6403, 6.7)
extrude "Extrude2" cut sketch "D clearance" along normal blind 5
work_plane "WorkPlane1" AlongDistance -38 ExtraOffset 0
sketch "Cam carrier hub" plane through (-38, 0, 0) normal (1, 0, 0) x axis (0, 0, -1)
  circle C1 centre (-30, 0) radius 14
extrude "Extrude1" new body sketch "Cam carrier hub" along normal blind 12.5 bodies "P32 External keyed cam carrier"
work_plane "WorkPlane2" AlongDistance -33 ExtraOffset 0
sketch "Full cam support fan" plane through (-33, 0, 0) normal (1, 0, 0) x axis (0, 0, -1)
  line L1 (-12.6727, 37.1586) -> (-30, 0)
  line L2 (-12.0268, 36.8506) -> (-12.6727, 37.1586)
  line L3 (-11.3864, 36.5313) -> (-12.0268, 36.8506)
  line L4 (-10.7517, 36.2009) -> (-11.3864, 36.5313)
  line L5 (-10.1228, 35.8594) -> (-10.7517, 36.2009)
  line L6 (-9.5, 35.507) -> (-10.1228, 35.8594)
  line L7 (-8.8834, 35.1439) -> (-9.5, 35.507)
  line L8 (-8.2733, 34.77) -> (-8.8834, 35.1439)
  line L9 (-7.6698, 34.3855) -> (-8.2733, 34.77)
  line L10 (-7.0731, 33.9905) -> (-7.6698, 34.3855)
  line L11 (-6.4834, 33.5852) -> (-7.0731, 33.9905)
  line L12 (-5.9008, 33.1697) -> (-6.4834, 33.5852)
  line L13 (-5.3256, 32.7441) -> (-5.9008, 33.1697)
  line L14 (-4.7579, 32.3084) -> (-5.3256, 32.7441)
  line L15 (-4.1979, 31.863) -> (-4.7579, 32.3084)
  line L16 (-3.6457, 31.4078) -> (-4.1979, 31.863)
  line L17 (-3.1016, 30.9431) -> (-3.6457, 31.4078)
  line L18 (-2.5656, 30.4689) -> (-3.1016, 30.9431)
  line L19 (-2.0381, 29.9855) -> (-2.5656, 30.4689)
  line L20 (-1.519, 29.4929) -> (-2.0381, 29.9855)
  line L21 (-1.0086, 28.9914) -> (-1.519, 29.4929)
  line L22 (-0.5071, 28.481) -> (-1.0086, 28.9914)
  line L23 (-0.0145, 27.9619) -> (-0.5071, 28.481)
  line L24 (0.4689, 27.4344) -> (-0.0145, 27.9619)
  line L25 (0.9431, 26.8984) -> (0.4689, 27.4344)
  line L26 (1.4078, 26.3543) -> (0.9431, 26.8984)
  line L27 (1.863, 25.8021) -> (1.4078, 26.3543)
  line L28 (2.3084, 25.2421) -> (1.863, 25.8021)
  line L29 (2.7441, 24.6744) -> (2.3084, 25.2421)
  line L30 (3.1697, 24.0992) -> (2.7441, 24.6744)
  line L31 (3.5852, 23.5166) -> (3.1697, 24.0992)
  line L32 (3.9905, 22.9269) -> (3.5852, 23.5166)
  line L33 (4.3855, 22.3302) -> (3.9905, 22.9269)
  line L34 (4.77, 21.7267) -> (4.3855, 22.3302)
  line L35 (5.1439, 21.1166) -> (4.77, 21.7267)
  line L36 (5.507, 20.5) -> (5.1439, 21.1166)
  line L37 (5.8594, 19.8772) -> (5.507, 20.5)
  line L38 (6.2009, 19.2483) -> (5.8594, 19.8772)
  line L39 (6.5313, 18.6136) -> (6.2009, 19.2483)
  line L40 (6.8506, 17.9732) -> (6.5313, 18.6136)
  line L41 (7.1586, 17.3273) -> (6.8506, 17.9732)
  line L42 (7.4554, 16.6762) -> (7.1586, 17.3273)
  line L43 (7.7407, 16.02) -> (7.4554, 16.6762)
  line L44 (8.0145, 15.3589) -> (7.7407, 16.02)
  line L45 (8.2768, 14.6931) -> (8.0145, 15.3589)
  line L46 (8.5274, 14.0228) -> (8.2768, 14.6931)
  line L47 (8.7663, 13.3483) -> (8.5274, 14.0228)
  line L48 (8.9933, 12.6697) -> (8.7663, 13.3483)
  line L49 (9.2085, 11.9872) -> (8.9933, 12.6697)
  line L50 (9.4117, 11.3011) -> (9.2085, 11.9872)
  line L51 (9.603, 10.6116) -> (9.4117, 11.3011)
  line L52 (9.7821, 9.9188) -> (9.603, 10.6116)
  line L53 (9.9492, 9.223) -> (9.7821, 9.9188)
  line L54 (10.1041, 8.5244) -> (9.9492, 9.223)
  line L55 (10.2467, 7.8232) -> (10.1041, 8.5244)
  line L56 (10.3771, 7.1196) -> (10.2467, 7.8232)
  line L57 (10.4952, 6.4138) -> (10.3771, 7.1196)
  line L58 (10.601, 5.7061) -> (10.4952, 6.4138)
  line L59 (10.6944, 4.9966) -> (10.601, 5.7061)
  line L60 (10.7754, 4.2857) -> (10.6944, 4.9966)
  line L61 (10.844, 3.5734) -> (10.7754, 4.2857)
  line L62 (10.9001, 2.86) -> (10.844, 3.5734)
  line L63 (10.9438, 2.1458) -> (10.9001, 2.86)
  line L64 (10.975, 1.4309) -> (10.9438, 2.1458)
  line L65 (10.9938, 0.7155) -> (10.975, 1.4309)
  line L66 (11, 0) -> (10.9938, 0.7155)
  line L67 (10.9938, -0.7155) -> (11, 0)
  line L68 (10.975, -1.4309) -> (10.9938, -0.7155)
  line L69 (10.9438, -2.1458) -> (10.975, -1.4309)
  line L70 (10.9001, -2.86) -> (10.9438, -2.1458)
  line L71 (10.844, -3.5734) -> (10.9001, -2.86)
  line L72 (10.7754, -4.2857) -> (10.844, -3.5734)
  line L73 (10.6944, -4.9966) -> (10.7754, -4.2857)
  line L74 (10.601, -5.7061) -> (10.6944, -4.9966)
  line L75 (10.4952, -6.4138) -> (10.601, -5.7061)
  line L76 (10.3771, -7.1196) -> (10.4952, -6.4138)
  line L77 (10.2467, -7.8232) -> (10.3771, -7.1196)
  line L78 (10.1041, -8.5244) -> (10.2467, -7.8232)
  line L79 (9.9492, -9.223) -> (10.1041, -8.5244)
  line L80 (9.7821, -9.9188) -> (9.9492, -9.223)
  line L81 (9.603, -10.6116) -> (9.7821, -9.9188)
  line L82 (9.4117, -11.3011) -> (9.603, -10.6116)
  line L83 (9.2085, -11.9872) -> (9.4117, -11.3011)
  line L84 (8.9933, -12.6697) -> (9.2085, -11.9872)
  line L85 (8.7663, -13.3483) -> (8.9933, -12.6697)
  line L86 (8.5274, -14.0228) -> (8.7663, -13.3483)
  line L87 (8.2768, -14.6931) -> (8.5274, -14.0228)
  line L88 (8.0145, -15.3589) -> (8.2768, -14.6931)
  line L89 (7.7407, -16.02) -> (8.0145, -15.3589)
  line L90 (7.4554, -16.6762) -> (7.7407, -16.02)
  line L91 (7.1586, -17.3273) -> (7.4554, -16.6762)
  line L92 (6.8506, -17.9732) -> (7.1586, -17.3273)
  line L93 (6.5313, -18.6136) -> (6.8506, -17.9732)
  line L94 (6.2009, -19.2483) -> (6.5313, -18.6136)
  line L95 (5.8594, -19.8772) -> (6.2009, -19.2483)
  line L96 (5.507, -20.5) -> (5.8594, -19.8772)
  line L97 (5.1439, -21.1166) -> (5.507, -20.5)
  line L98 (4.77, -21.7267) -> (5.1439, -21.1166)
  line L99 (4.3855, -22.3302) -> (4.77, -21.7267)
  line L100 (3.9905, -22.9269) -> (4.3855, -22.3302)
  line L101 (3.5852, -23.5166) -> (3.9905, -22.9269)
  line L102 (3.1697, -24.0992) -> (3.5852, -23.5166)
  line L103 (2.7441, -24.6744) -> (3.1697, -24.0992)
  line L104 (2.3084, -25.2421) -> (2.7441, -24.6744)
  line L105 (1.863, -25.8021) -> (2.3084, -25.2421)
  line L106 (1.4078, -26.3543) -> (1.863, -25.8021)
  line L107 (0.9431, -26.8984) -> (1.4078, -26.3543)
  line L108 (0.4689, -27.4344) -> (0.9431, -26.8984)
  line L109 (-0.0145, -27.9619) -> (0.4689, -27.4344)
  line L110 (-0.5071, -28.481) -> (-0.0145, -27.9619)
  line L111 (-1.0086, -28.9914) -> (-0.5071, -28.481)
  line L112 (-1.519, -29.4929) -> (-1.0086, -28.9914)
  line L113 (-2.0381, -29.9855) -> (-1.519, -29.4929)
  line L114 (-2.5656, -30.4689) -> (-2.0381, -29.9855)
  line L115 (-3.1016, -30.9431) -> (-2.5656, -30.4689)
  line L116 (-3.6457, -31.4078) -> (-3.1016, -30.9431)
  line L117 (-4.1979, -31.863) -> (-3.6457, -31.4078)
  line L118 (-4.7579, -32.3084) -> (-4.1979, -31.863)
  line L119 (-5.3256, -32.7441) -> (-4.7579, -32.3084)
  line L120 (-5.9008, -33.1697) -> (-5.3256, -32.7441)
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extrude "Extrude2" add sketch "Full cam support fan" along normal blind 7.5
work_plane "WorkPlane3" AlongDistance -38.1 ExtraOffset 0
sketch "Left shaft keyed socket" plane through (-38.1, 0, 0) normal (1, 0, 0) x axis (0, 0, -1)
  line L1 (-33.6497, 4.95) -> (-26.3503, 4.95)
  arc A1 centre (-30, 0) radius 6.15 clockwise from (-26.3503, 4.95) to (-33.6497, 4.95)
extrude "Extrude3" cut sketch "Left shaft keyed socket" along normal blind 12.7
work_plane "WorkPlane4" AlongDistance -25.8 ExtraOffset 0
sketch "Flange clearance and axial float relief" plane through (-25.8, 0, 0) normal (1, 0, 0) x axis (0, 0, -1)
  circle C1 centre (-30, 0) radius 13
work_plane "WorkPlane5" AlongDistance -37 ExtraOffset 0
sketch "Carrier clamp accessible boss" plane through (-37, 0, 0) normal (1, 0, 0) x axis (0, 0, -1)
  line L1 (-25, 14.8) -> (-25, 11.5)
  line L2 (-35, 14.8) -> (-25, 14.8)
  line L3 (-35, 11.5) -> (-35, 14.8)
  line L4 (-25, 11.5) -> (-35, 11.5)
extrude "Extrude5" add sketch "Carrier clamp accessible boss" along normal blind 9
work_plane "WorkPlane6" AlongDistance 8 ExtraOffset 0
sketch "Carrier clamp insert" plane through (0, 8, 0) normal (0, 1, 0) x axis (1, 0, 0)
  circle C1 centre (-32.5, -30) radius 2
extrude "Extrude6" cut sketch "Carrier clamp insert" along normal blind 6.9
work_plane "WorkPlane7" AlongDistance 4.9 ExtraOffset 0
sketch "Carrier clamp tip passage" plane through (0, 4.9, 0) normal (0, 1, 0) x axis (1, 0, 0)
  circle C1 centre (-32.5, -30) radius 1.7
extrude "Extrude7" cut sketch "Carrier clamp tip passage" along normal blind 3.2
work_plane "WorkPlane8" AlongDistance 8 ExtraOffset 0
sketch "Carrier radial bore negative X roof" plane through (0, 8, 0) normal (0, 1, 0) x axis (1, 0, 0)
  line L1 (-33.9142, -31.4142) -> (-33.9142, -28.5858)
  line L2 (-35.3284, -30) -> (-33.9142, -31.4142)
  line L3 (-33.9142, -28.5858) -> (-35.3284, -30)
extrude "Extrude8" cut sketch "Carrier radial bore negative X roof" along normal blind 6.9
work_plane "WorkPlane9" AlongDistance 4.9 ExtraOffset 0
sketch "Carrier radial bore negative X roof (1)" plane through (0, 4.9, 0) normal (0, 1, 0) x axis (1, 0, 0)
  line L1 (-33.7021, -31.2021) -> (-33.7021, -28.7979)
  line L2 (-34.9042, -30) -> (-33.7021, -31.2021)
  line L3 (-33.7021, -28.7979) -> (-34.9042, -30)
extrude "Extrude9" cut sketch "Carrier radial bore negative X roof (1)" along normal blind 3.2
work_plane "WorkPlane1" AlongDistance 4.8 ExtraOffset 0
sketch "Carrier clamp M3x10" plane through (0, 4.8, 0) normal (0, 1, 0) x axis (1, 0, 0)
  circle C1 centre (-32.5, -30) radius 1.5
extrude "Extrude1" new body sketch "Carrier clamp M3x10" along normal blind 10 bodies "HARDWARE Carrier clamp M3x10"
work_plane "WorkPlane2" AlongDistance 14.8 ExtraOffset 0
sketch "Button head" plane through (0, 14.8, 0) normal (0, 1, 0) x axis (1, 0, 0)
  circle C1 centre (-32.5, -30) radius 2.75
extrude "Extrude2" add sketch "Button head" along normal blind 3
work_plane "WorkPlane10" AlongDistance -33.1 ExtraOffset 0
sketch "Face-access cam insert" plane through (-33.1, 0, 0) normal (1, 0, 0) x axis (0, 0, -1)
  circle C1 centre (-4.5442, 25.4558) radius 2
extrude "Extrude10" cut sketch "Face-access cam insert" along normal blind 6.9
work_plane "WorkPlane11" AlongDistance -33.1 ExtraOffset 0
sketch "Face-access cam insert (1)" plane through (-33.1, 0, 0) normal (1, 0, 0) x axis (0, 0, -1)
  circle C1 centre (6, 0) radius 2
extrude "Extrude11" cut sketch "Face-access cam insert (1)" along normal blind 6.9
work_plane "WorkPlane12" AlongDistance -33.1 ExtraOffset 0
sketch "Face-access cam insert (2)" plane through (-33.1, 0, 0) normal (1, 0, 0) x axis (0, 0, -1)
  circle C1 centre (-4.5442, -25.4558) radius 2
extrude "Extrude12" cut sketch "Face-access cam insert (2)" along normal blind 6.9
position "Position7"
work_plane "WorkPlane13" AlongDistance -7.1 ExtraOffset 0
sketch "Restore exact stop nose contact" plane through (-7.1, 0, 0) normal (1, 0, 0) x axis (0, 0, -1)
  line L1 (0, -6) -> (0, -5)
  line L2 (-15, -11) -> (0, -6)
  line L3 (0, -5) -> (-15, -11)
extrude "Extrude13" cut sketch "Restore exact stop nose contact" along normal blind 14.2
work_plane "WorkPlane14" AlongDistance -7.1 ExtraOffset 0
sketch "Restore exact stop nose contact (1)" plane through (-7.1, 0, 0) normal (1, 0, 0) x axis (0, 0, -1)
  line L1 (0, 6) -> (0, 5)
  line L2 (-15, 11) -> (0, 6)
  line L3 (0, 5) -> (-15, 11)
extrude "Extrude14" cut sketch "Restore exact stop nose contact (1)" along normal blind 14.2
work_plane "WorkPlane26" AlongDistance -24 ExtraOffset 0
sketch "Continuous lower cassette foundation" plane through (-24, 0, 0) normal (1, 0, 0) x axis (0, 0, -1)
  line L1 (45, 74.5) -> (45, -74.5)
  line L2 (33, 74.5) -> (45, 74.5)
  line L3 (33, -74.5) -> (33, 74.5)
  line L4 (45, -74.5) -> (33, -74.5)
extrude "Extrude26" add sketch "Continuous lower cassette foundation" along normal blind 12
work_plane "WorkPlane27" AlongDistance -33.5 ExtraOffset 0
sketch "Lowered cassette mounting boss" plane through (-33.5, 0, 0) normal (1, 0, 0) x axis (0, 0, -1)
  circle C1 centre (39, -55) radius 6
extrude "Extrude27" add sketch "Lowered cassette mounting boss" along normal blind 9.5
work_plane "WorkPlane28" AlongDistance -33.6 ExtraOffset 0
sketch "Cassette insert pocket (2)" plane through (-33.6, 0, 0) normal (1, 0, 0) x axis (0, 0, -1)
  circle C1 centre (39, -55) radius 2
extrude "Extrude28" cut sketch "Cassette insert pocket (2)" along normal blind 6.9
work_plane "WorkPlane29" AlongDistance -33.5 ExtraOffset 0
sketch "Lowered cassette mounting boss (1)" plane through (-33.5, 0, 0) normal (1, 0, 0) x axis (0, 0, -1)
  circle C1 centre (39, -15) radius 6
extrude "Extrude29" add sketch "Lowered cassette mounting boss (1)" along normal blind 9.5
work_plane "WorkPlane30" AlongDistance -33.6 ExtraOffset 0
sketch "Cassette insert pocket (3)" plane through (-33.6, 0, 0) normal (1, 0, 0) x axis (0, 0, -1)
  circle C1 centre (39, -15) radius 2
extrude "Extrude30" cut sketch "Cassette insert pocket (3)" along normal blind 6.9
work_plane "WorkPlane31" AlongDistance -24.1 ExtraOffset 0
sketch "Flush stop head clears external cam sweep" plane through (-24.1, 0, 0) normal (1, 0, 0) x axis (0, 0, -1)
  circle C1 centre (-22.8923, -36.3109) radius 3.1
extrude "Extrude31" cut sketch "Flush stop head clears external cam sweep" along normal blind 3.1
work_plane "WorkPlane1" AlongDistance -21 ExtraOffset 0
sketch "Stop M3x16 -1" plane through (-21, 0, 0) normal (1, 0, 0) x axis (0, 0, -1)
  circle C1 centre (-22.8923, -36.3109) radius 1.5
extrude "Extrude1" new body sketch "Stop M3x16 -1" along normal blind 16 bodies "HARDWARE Stop M3x16 -1"
work_plane "WorkPlane2" AlongDistance -24 ExtraOffset 0
sketch "Button head" plane through (-24, 0, 0) normal (1, 0, 0) x axis (0, 0, -1)
  circle C1 centre (-22.8923, -36.3109) radius 2.75
extrude "Extrude2" add sketch "Button head" along normal blind 3
work_plane "WorkPlane32" AlongDistance -24.1 ExtraOffset 0
sketch "Flush stop head clears external cam sweep (1)" plane through (-24.1, 0, 0) normal (1, 0, 0) x axis (0, 0, -1)
  circle C1 centre (-22.8923, 36.3109) radius 3.1
extrude "Extrude32" cut sketch "Flush stop head clears external cam sweep (1)" along normal blind 3.1
work_plane "WorkPlane1" AlongDistance -21 ExtraOffset 0
sketch "Stop M3x16 1" plane through (-21, 0, 0) normal (1, 0, 0) x axis (0, 0, -1)
  circle C1 centre (-22.8923, 36.3109) radius 1.5
extrude "Extrude1" new body sketch "Stop M3x16 1" along normal blind 16 bodies "HARDWARE Stop M3x16 1"
work_plane "WorkPlane2" AlongDistance -24 ExtraOffset 0
sketch "Button head" plane through (-24, 0, 0) normal (1, 0, 0) x axis (0, 0, -1)
  circle C1 centre (-22.8923, 36.3109) radius 2.75
extrude "Extrude2" add sketch "Button head" along normal blind 3
work_plane "WorkPlane33" AlongDistance -24 ExtraOffset 0
sketch "Close superseded spring block hole" plane through (-24, 0, 0) normal (1, 0, 0) x axis (0, 0, -1)
  circle C1 centre (-14, -48) radius 1.71
extrude "Extrude33" add sketch "Close superseded spring block hole" along normal blind 12
work_plane "WorkPlane34" AlongDistance -24.1 ExtraOffset 0
sketch "Inboard spring block mounting clearance" plane through (-24.1, 0, 0) normal (1, 0, 0) x axis (0, 0, -1)
  circle C1 centre (-14, -54) radius 1.7
extrude "Extrude34" cut sketch "Inboard spring block mounting clearance" along normal blind 12.2
work_plane "WorkPlane1" AlongDistance -49.2 ExtraOffset 0
sketch "Cam-clear follower support plate" plane through (-49.2, 0, 0) normal (1, 0, 0) x axis (0, 0, -1)
  line L1 (46, -5) -> (46, -65)
  line L2 (30, -5) -> (46, -5)
  line L3 (15, -25) -> (30, -5)
  line L4 (15, -65) -> (15, -25)
  line L5 (46, -65) -> (15, -65)
extrude "Extrude1" new body sketch "Cam-clear follower support plate" along normal blind 4 bodies "P33 Integral follower support cassette"
work_plane "WorkPlane2" AlongDistance -47.2 ExtraOffset 0
sketch "Captured axle blind seat bridge" plane through (-47.2, 0, 0) normal (1, 0, 0) x axis (0, 0, -1)
  circle C1 centre (23, -35) radius 4.15
extrude "Extrude2" cut sketch "Captured axle blind seat bridge" along normal blind 2.1
work_plane "WorkPlane3" AlongDistance -49.3 ExtraOffset 0
sketch "Support screw passage" plane through (-49.3, 0, 0) normal (1, 0, 0) x axis (0, 0, -1)
  circle C1 centre (39, -55) radius 1.7
extrude "Extrude3" cut sketch "Support screw passage" along normal blind 4.2
work_plane "WorkPlane4" AlongDistance -49.3 ExtraOffset 0
sketch "Recessed cap head" plane through (-49.3, 0, 0) normal (1, 0, 0) x axis (0, 0, -1)
  circle C1 centre (39, -55) radius 3.1
extrude "Extrude4" cut sketch "Recessed cap head" along normal blind 2.1
work_plane "WorkPlane1" AlongDistance -47.2 ExtraOffset 0
sketch "Cassette M3x20 -55" plane through (-47.2, 0, 0) normal (1, 0, 0) x axis (0, 0, -1)
  circle C1 centre (39, -55) radius 1.5
extrude "Extrude1" new body sketch "Cassette M3x20 -55" along normal blind 20 bodies "HARDWARE Cassette M3x20 -55"
work_plane "WorkPlane2" AlongDistance -50.2 ExtraOffset 0
sketch "Button head" plane through (-50.2, 0, 0) normal (1, 0, 0) x axis (0, 0, -1)
  circle C1 centre (39, -55) radius 2.75
extrude "Extrude2" add sketch "Button head" along normal blind 3
work_plane "WorkPlane5" AlongDistance -49.3 ExtraOffset 0
sketch "Support screw passage (1)" plane through (-49.3, 0, 0) normal (1, 0, 0) x axis (0, 0, -1)
  circle C1 centre (39, -15) radius 1.7
extrude "Extrude5" cut sketch "Support screw passage (1)" along normal blind 4.2
work_plane "WorkPlane6" AlongDistance -49.3 ExtraOffset 0
sketch "Recessed cap head (1)" plane through (-49.3, 0, 0) normal (1, 0, 0) x axis (0, 0, -1)
  circle C1 centre (39, -15) radius 3.1
extrude "Extrude6" cut sketch "Recessed cap head (1)" along normal blind 2.1
work_plane "WorkPlane1" AlongDistance -47.2 ExtraOffset 0
sketch "Cassette M3x20 -15" plane through (-47.2, 0, 0) normal (1, 0, 0) x axis (0, 0, -1)
  circle C1 centre (39, -15) radius 1.5
extrude "Extrude1" new body sketch "Cassette M3x20 -15" along normal blind 20 bodies "HARDWARE Cassette M3x20 -15"
work_plane "WorkPlane2" AlongDistance -50.2 ExtraOffset 0
sketch "Button head" plane through (-50.2, 0, 0) normal (1, 0, 0) x axis (0, 0, -1)
  circle C1 centre (39, -15) radius 2.75
extrude "Extrude2" add sketch "Button head" along normal blind 3
work_plane "WorkPlane7" AlongDistance -49.3 ExtraOffset 0
sketch "Service screw absolute minus4 degrees" plane through (-49.3, 0, 0) normal (1, 0, 0) x axis (0, 0, -1)
  circle C1 centre (21.6049, -54.9513) radius 1.7
extrude "Extrude7" cut sketch "Service screw absolute minus4 degrees" along normal blind 4.2
work_plane "WorkPlane1" AlongDistance -47.05 ExtraOffset 0
sketch "Captured axle" plane through (-47.05, 0, 0) normal (1, 0, 0) x axis (0, 0, -1)
  circle C1 centre (23, -35) radius 4
extrude "Extrude1" new body sketch "Captured axle" along normal blind 24.9 bodies "P25 Captured follower axle lower half"
work_plane "WorkPlane2" AlongDistance -47.1 ExtraOffset 0
sketch "Flat split face" plane through (-47.1, 0, 0) normal (1, 0, 0) x axis (0, 0, -1)
  line L1 (28, -30) -> (28, -35)
  line L2 (18, -30) -> (28, -30)
  line L3 (18, -35) -> (18, -30)
  line L4 (28, -35) -> (18, -35)
extrude "Extrude2" cut sketch "Flat split face" along normal blind 25
work_plane "WorkPlane1" AlongDistance -47.05 ExtraOffset 0
sketch "Captured axle" plane through (-47.05, 0, 0) normal (1, 0, 0) x axis (0, 0, -1)
  circle C1 centre (23, -35) radius 4
extrude "Extrude1" new body sketch "Captured axle" along normal blind 24.9 bodies "P26 Captured follower axle upper half"
work_plane "WorkPlane2" AlongDistance -47.1 ExtraOffset 0
sketch "Flat split face" plane through (-47.1, 0, 0) normal (1, 0, 0) x axis (0, 0, -1)
  line L1 (28, -35) -> (28, -40)
  line L2 (18, -35) -> (28, -35)
  line L3 (18, -40) -> (18, -35)
  line L4 (28, -40) -> (18, -40)
extrude "Extrude2" cut sketch "Flat split face" along normal blind 25
work_plane "WorkPlane1" AlongDistance -29 ExtraOffset 0
sketch "Follower axial spacer" plane through (-29, 0, 0) normal (1, 0, 0) x axis (0, 0, -1)
  circle C1 centre (23, -35) radius 6
extrude "Extrude1" new body sketch "Follower axial spacer" along normal blind 4.8 bodies "P21 Follower inner thrust spacer"
work_plane "WorkPlane2" AlongDistance -29.1 ExtraOffset 0
sketch "Pivot clearance" plane through (-29.1, 0, 0) normal (1, 0, 0) x axis (0, 0, -1)
  circle C1 centre (23, -35) radius 4.15
extrude "Extrude2" cut sketch "Pivot clearance" along normal blind 5
work_plane "WorkPlane1" AlongDistance -49 ExtraOffset 0
sketch "Outboard spring reaction body" plane through (-49, 0, 0) normal (1, 0, 0) x axis (0, 0, -1)
  line L1 (-3, -50) -> (-3, -66)
  line L2 (-24, -50) -> (-3, -50)
  line L3 (-24, -66) -> (-24, -50)
  line L4 (-3, -66) -> (-24, -66)
extrude "Extrude1" new body sketch "Outboard spring reaction body" along normal blind 25 bodies "P13 Outboard spring reaction block"
work_plane "WorkPlane2" AlongDistance 2.9 ExtraOffset 0
sketch "Underside M3 insert" plane through (0, 0, 2.9) normal (0, 0, 1) x axis (1, 0, 0)
  circle C1 centre (-45, -55) radius 2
